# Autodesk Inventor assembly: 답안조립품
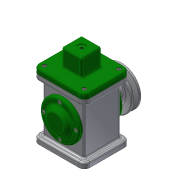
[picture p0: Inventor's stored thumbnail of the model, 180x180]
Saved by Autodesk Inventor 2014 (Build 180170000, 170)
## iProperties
Created: 2017-08
Part Number: 답안조립품
Document SubType Name: Assembly
Designer: user
Author: user
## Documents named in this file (18)
- C:\Users\user\Desktop\470808V1002\답안조립품.iam
- C:\Users\user\Desktop\470808V1002\본체.ipt
- C:\Users\user\Desktop\470808V1002\E-링.ipt
- C:\Users\user\Desktop\470808V1002\V-벨트풀리.ipt
- C:\Users\user\Desktop\470808V1002\덮개.ipt
- C:\Users\user\Desktop\470808V1002\뒤커버.ipt
- C:\Users\user\Desktop\470808V1002\링크.ipt
- C:\Users\user\Desktop\470808V1002\베어링 17 x 40 x 12.ipt
- C:\Users\user\Desktop\470808V1002\볼트 M4 x 8.ipt
- C:\Users\user\Desktop\470808V1002\볼트 M4 x 10.ipt
- C:\Users\user\Desktop\470808V1002\슬라이더.ipt
- C:\Users\user\Desktop\470808V1002\앞커버.ipt
- C:\Users\user\Desktop\470808V1002\오일 실 17 30 8.ipt
- C:\Users\user\Desktop\470808V1002\와셔 4x16.ipt
- C:\Users\user\Desktop\470808V1002\클레비스 핀 6 x 22.ipt
- 클레비스 핀 6 x 22.ipt
- C:\Users\user\Desktop\470808V1002\키 4 x 4 x 12.ipt
- C:\Users\user\Desktop\470808V1002\편심축.ipt
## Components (2 placed, 2 different names)
1. E-링:1
2. V-벨트풀리:1
